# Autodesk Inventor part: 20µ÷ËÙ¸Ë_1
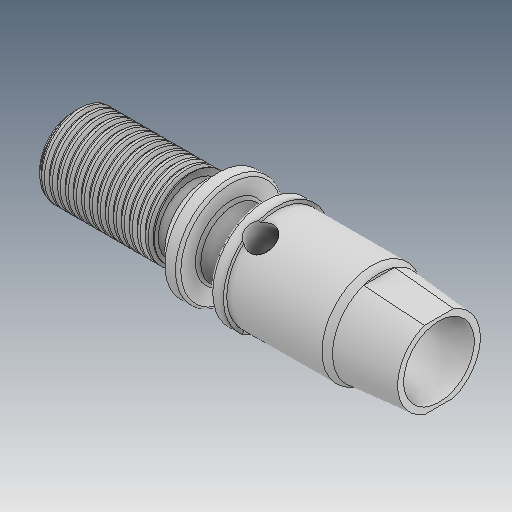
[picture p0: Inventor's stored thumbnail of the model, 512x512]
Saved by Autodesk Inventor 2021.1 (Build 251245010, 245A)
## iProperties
Created: 2019-05
Part Number: 20µ÷ËÙ¸Ë_1
Material: Ogólny
Document SubType Name: Modeling
Designer: user
Density: 1 g/cm^3
Appearance: Domyślna
Author: user
Revision Number: ÈÎºÎ
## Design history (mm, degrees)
feature "ÊäÈë1"
node "Bryła1"
